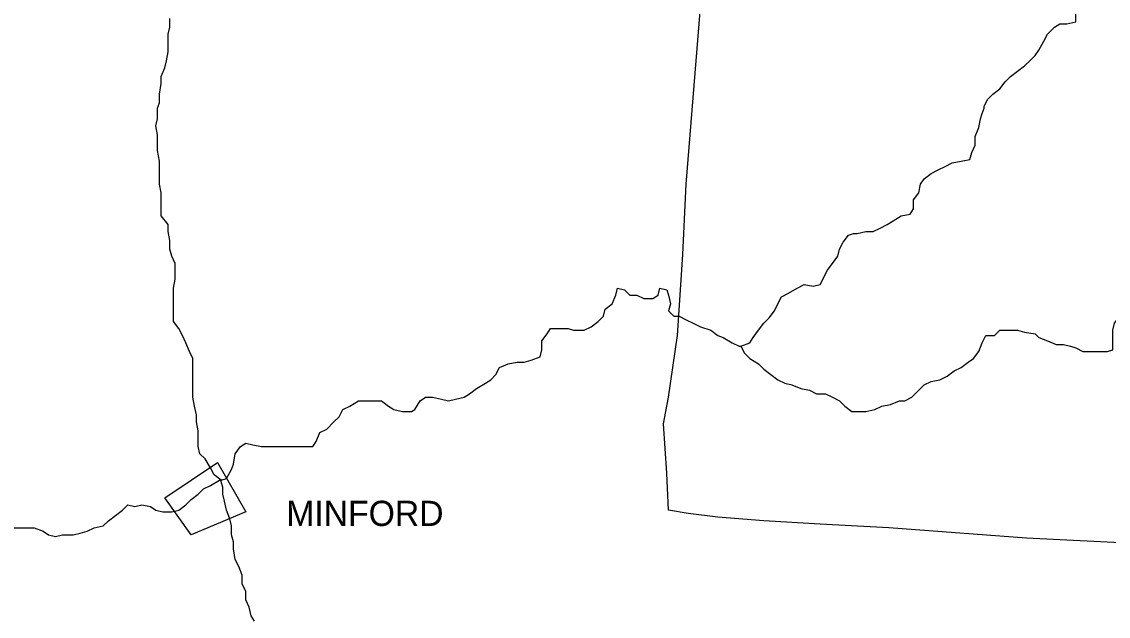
# Model space of a CAD drawing. Extents: x 0 to 40.2, y 0 to 22.
# Drawn here: x 6.366 to 7.207, y 16.868 to 17.328 of the extents above; entities that cross this region are included whole.
import ezdxf

# ---------------------------------------------------------------- set-up
doc = ezdxf.new("R2010")
doc.units = 0
doc.layers.add('Default', color=7, linetype='Continuous')

msp = doc.modelspace()

# ---------------------------------------------------------------- linework, layer by layer
at = {"layer": 'Default'}
for points in [[(7.25777, 16.92255), (7.14325, 16.92801), (7.0369, 16.93619), (6.98373, 16.93891), (6.9401, 16.94164), (6.90465, 16.94437), (6.88147, 16.94709), (6.86647, 16.94982), (6.86511, 16.97845), (6.86238, 17.01663), (6.86511, 17.03026), (6.86647, 17.03708), (6.87329, 17.0848), (6.87738, 17.14752), (6.88011, 17.20205), (6.88556, 17.26886), (6.89238, 17.35476), (6.78739, 17.36294), (6.70286, 17.36839)], [(6.47244, 17.20751), (6.47244, 17.21432), (6.47244, 17.21978), (6.47108, 17.22796), (6.47108, 17.23477), (6.47108, 17.24023), (6.46972, 17.24705), (6.47108, 17.2525), (6.47108, 17.26068), (6.47244, 17.26477), (6.47244, 17.27159), (6.47381, 17.27977), (6.47381, 17.28522), (6.47653, 17.29204), (6.4779, 17.29749), (6.47926, 17.30431), (6.47926, 17.30976), (6.47926, 17.31794), (6.48062, 17.3234), (6.48062, 17.33021)], [(7.11053, 17.26204), (7.11325, 17.2675), (7.11734, 17.27159), (7.1228, 17.27568), (7.12689, 17.28113), (7.13098, 17.28522), (7.13643, 17.28931), (7.14188, 17.2934), (7.14597, 17.29749), (7.15006, 17.30158), (7.15279, 17.30567), (7.15688, 17.31249), (7.15961, 17.31794), (7.16506, 17.3234), (7.16915, 17.32612), (7.17461, 17.32612), (7.18142, 17.32749), (7.18142, 17.3343)], [(7.01236, 17.16388), (7.01918, 17.16524), (7.02463, 17.16524), (7.03008, 17.16797), (7.03554, 17.17069), (7.04235, 17.17478), (7.04644, 17.17751), (7.05326, 17.17887), (7.05599, 17.18296), (7.05599, 17.18978), (7.06008, 17.19524), (7.06144, 17.20205), (7.06417, 17.20614), (7.06962, 17.21023), (7.07508, 17.21296), (7.08053, 17.21569), (7.08598, 17.21841), (7.0928, 17.21978), (7.09962, 17.22114), (7.10098, 17.22659), (7.10371, 17.23205), (7.10371, 17.23887), (7.10644, 17.24568), (7.1078, 17.2525), (7.10916, 17.25659), (7.11053, 17.26068), (7.11053, 17.26204)], [(6.49835, 17.06707), (6.49562, 17.07253), (6.4929, 17.07934), (6.49017, 17.0848), (6.48744, 17.09025), (6.48335, 17.09571), (6.48335, 17.10116), (6.48335, 17.10798), (6.48335, 17.11479), (6.48335, 17.12161), (6.48472, 17.12843), (6.48472, 17.13388), (6.48472, 17.1407), (6.48199, 17.14615), (6.48062, 17.15161), (6.48062, 17.15842), (6.47926, 17.16524), (6.47926, 17.17069), (6.47381, 17.17751), (6.47381, 17.1816), (6.47381, 17.18978), (6.47381, 17.19524), (6.47244, 17.20205), (6.47244, 17.20614), (6.47244, 17.20751)], [(6.92237, 17.07662), (6.92919, 17.07934), (6.93192, 17.08344), (6.93601, 17.08889), (6.9401, 17.09434), (6.94419, 17.09843), (6.94828, 17.10389), (6.95101, 17.10934), (6.95373, 17.11479), (6.95919, 17.11752), (6.966, 17.12161), (6.97146, 17.12434), (6.97827, 17.12297), (6.98373, 17.12434), (6.98645, 17.12979), (6.98918, 17.13525), (6.99327, 17.1407), (6.99736, 17.14615), (6.99872, 17.15161), (7.00145, 17.15706), (7.00554, 17.16251), (7.00963, 17.16388), (7.01236, 17.16388)], [(6.70832, 17.03708), (6.71241, 17.03981), (6.71786, 17.0439), (6.72468, 17.04799), (6.72877, 17.05071), (6.73286, 17.0548), (6.73558, 17.06026), (6.7424, 17.06298), (6.74922, 17.06435), (6.75467, 17.06435), (6.76013, 17.06571), (6.76694, 17.06844), (6.76831, 17.07389), (6.76831, 17.08071), (6.7724, 17.08616), (6.77512, 17.09025), (6.78194, 17.09025), (6.78876, 17.09025), (6.79285, 17.08889), (6.80103, 17.08889), (6.80648, 17.09162), (6.81194, 17.09571), (6.81603, 17.0998), (6.81739, 17.10525), (6.82284, 17.10934), (6.82557, 17.11616), (6.82693, 17.12161), (6.83239, 17.12025), (6.83648, 17.11616), (6.84193, 17.11616), (6.84193, 17.11616), (6.84193, 17.11616)], [(6.84193, 17.11616), (6.84739, 17.11343), (6.8542, 17.11343), (6.85829, 17.11616), (6.85966, 17.12161), (6.86511, 17.12025), (6.86647, 17.11616), (6.86784, 17.10934), (6.86647, 17.10389), (6.87056, 17.0998), (6.87465, 17.0998)], [(7.18142, 17.07525), (7.18688, 17.07253), (7.19369, 17.07253), (7.19915, 17.07253), (7.20596, 17.07253), (7.21005, 17.07389), (7.21005, 17.08071), (7.21005, 17.08889), (7.21142, 17.09434), (7.21551, 17.0998), (7.21824, 17.10389), (7.21824, 17.10389)], [(6.87465, 17.0998), (6.88011, 17.09707), (6.88556, 17.09434), (6.89101, 17.09162), (6.8992, 17.08889), (6.90465, 17.0848), (6.90874, 17.08344), (6.91556, 17.07934), (6.92101, 17.07662), (6.92237, 17.07662), (6.92237, 17.07662)], [(7.05463, 17.03708), (7.06008, 17.04253), (7.06417, 17.04662), (7.06962, 17.04935), (7.07644, 17.05071), (7.08189, 17.05344), (7.08735, 17.05753), (7.0928, 17.06026), (7.09825, 17.06435), (7.10234, 17.06707), (7.10644, 17.07253), (7.10916, 17.07934), (7.11189, 17.0848), (7.11871, 17.0848), (7.1228, 17.08889), (7.1228, 17.08889)], [(7.1228, 17.08889), (7.12825, 17.08889), (7.13643, 17.08889), (7.14188, 17.08753), (7.15006, 17.08616), (7.15279, 17.08344), (7.15961, 17.08071), (7.16643, 17.07798), (7.17188, 17.07798), (7.17733, 17.07662), (7.18142, 17.07525), (7.18142, 17.07525)], [(6.92237, 17.07662), (6.9251, 17.07116), (6.92919, 17.06707), (6.93601, 17.06298), (6.9401, 17.05889), (6.94555, 17.0548), (6.95101, 17.05071), (6.95646, 17.04799), (6.96191, 17.04662), (6.96873, 17.0439), (6.97555, 17.04253), (6.981, 17.03981), (6.98782, 17.03981), (6.99327, 17.03708), (6.99872, 17.03435), (7.00282, 17.03026), (7.00827, 17.02617), (7.01372, 17.02617), (7.01918, 17.02617), (7.02599, 17.02753), (7.03145, 17.03026), (7.03826, 17.03163), (7.04508, 17.03435), (7.04917, 17.03435), (7.05463, 17.03708), (7.05463, 17.03708)], [(6.52016, 16.973), (6.51471, 16.97709), (6.51198, 16.98254), (6.50789, 16.98936), (6.5038, 16.99345), (6.50244, 16.9989), (6.50244, 17.00572), (6.50244, 17.01117), (6.50108, 17.01799), (6.50108, 17.02344), (6.49971, 17.03026), (6.49835, 17.03708), (6.49835, 17.0439), (6.49835, 17.05071), (6.49835, 17.05617), (6.49835, 17.06298), (6.49835, 17.06707)], [(6.59106, 16.9989), (6.59379, 17.00299), (6.59652, 17.00981), (6.60197, 17.01254), (6.60742, 17.01799), (6.61151, 17.02208), (6.61424, 17.02753), (6.61969, 17.03026), (6.62651, 17.03435), (6.63196, 17.03435), (6.63742, 17.03435), (6.64424, 17.03435), (6.64969, 17.03026), (6.65378, 17.02753), (6.6606, 17.02617), (6.66741, 17.02617), (6.67014, 17.02753), (6.67423, 17.03435), (6.67832, 17.03708), (6.68377, 17.03708), (6.69059, 17.03572), (6.69605, 17.03435), (6.7015, 17.03572), (6.70832, 17.03708)], [(6.52016, 16.973), (6.52425, 16.97436), (6.52834, 16.98118), (6.52971, 16.98527), (6.53107, 16.99345), (6.53516, 16.9989), (6.53925, 17.00163), (6.54471, 17.00027), (6.55152, 16.9989), (6.55698, 16.9989), (6.56379, 16.9989), (6.57061, 16.9989), (6.57743, 16.9989), (6.58424, 16.9989), (6.5897, 16.9989), (6.59106, 16.9989)], [(6.47653, 16.95936), (6.51744, 16.98663), (6.53925, 16.94846), (6.49699, 16.93073), (6.47653, 16.95936)], [(6.392, 16.92937), (6.39746, 16.93073), (6.40564, 16.93073), (6.41109, 16.9321), (6.41654, 16.93346), (6.422, 16.93619), (6.42881, 16.93755), (6.43291, 16.94164), (6.43836, 16.94573), (6.44381, 16.94982), (6.4479, 16.95391), (6.45336, 16.95255), (6.45881, 16.95391), (6.46563, 16.95255), (6.46972, 16.94982), (6.47517, 16.94846), (6.48199, 16.94846), (6.48744, 16.94982), (6.4929, 16.95391), (6.49699, 16.958), (6.50244, 16.96209), (6.50653, 16.96618), (6.51198, 16.96891), (6.5188, 16.973), (6.52016, 16.973)], [(6.54607, 16.86392), (6.54334, 16.86801), (6.54198, 16.87483), (6.53925, 16.88029), (6.53925, 16.8871), (6.53653, 16.89256), (6.53653, 16.89937), (6.5338, 16.90619), (6.53107, 16.91164), (6.52971, 16.91982), (6.52971, 16.92528), (6.52834, 16.93073), (6.52834, 16.93755), (6.52698, 16.943), (6.52425, 16.94982), (6.52289, 16.95664), (6.52153, 16.96209), (6.52153, 16.96754), (6.52016, 16.97163), (6.52016, 16.973)], [(6.31565, 16.87892), (6.31565, 16.88438), (6.31838, 16.89256), (6.31838, 16.89937), (6.3211, 16.90346), (6.32247, 16.91028), (6.32519, 16.91573), (6.32656, 16.92119), (6.33065, 16.92664), (6.33338, 16.9321), (6.33883, 16.93346), (6.34565, 16.93482), (6.3511, 16.93619), (6.35792, 16.93619), (6.36473, 16.93619), (6.37019, 16.93619), (6.37564, 16.93619), (6.38246, 16.93346), (6.38655, 16.93073), (6.392, 16.92937), (6.392, 16.92937)]]:
    msp.add_lwpolyline(points, dxfattribs=at)

# ---------------------------------------------------------------- texts
msp.add_text('MINFORD', height=0.019502, dxfattribs=at).set_placement((6.57061, 16.93755))

doc.saveas('drawing.dxf')
